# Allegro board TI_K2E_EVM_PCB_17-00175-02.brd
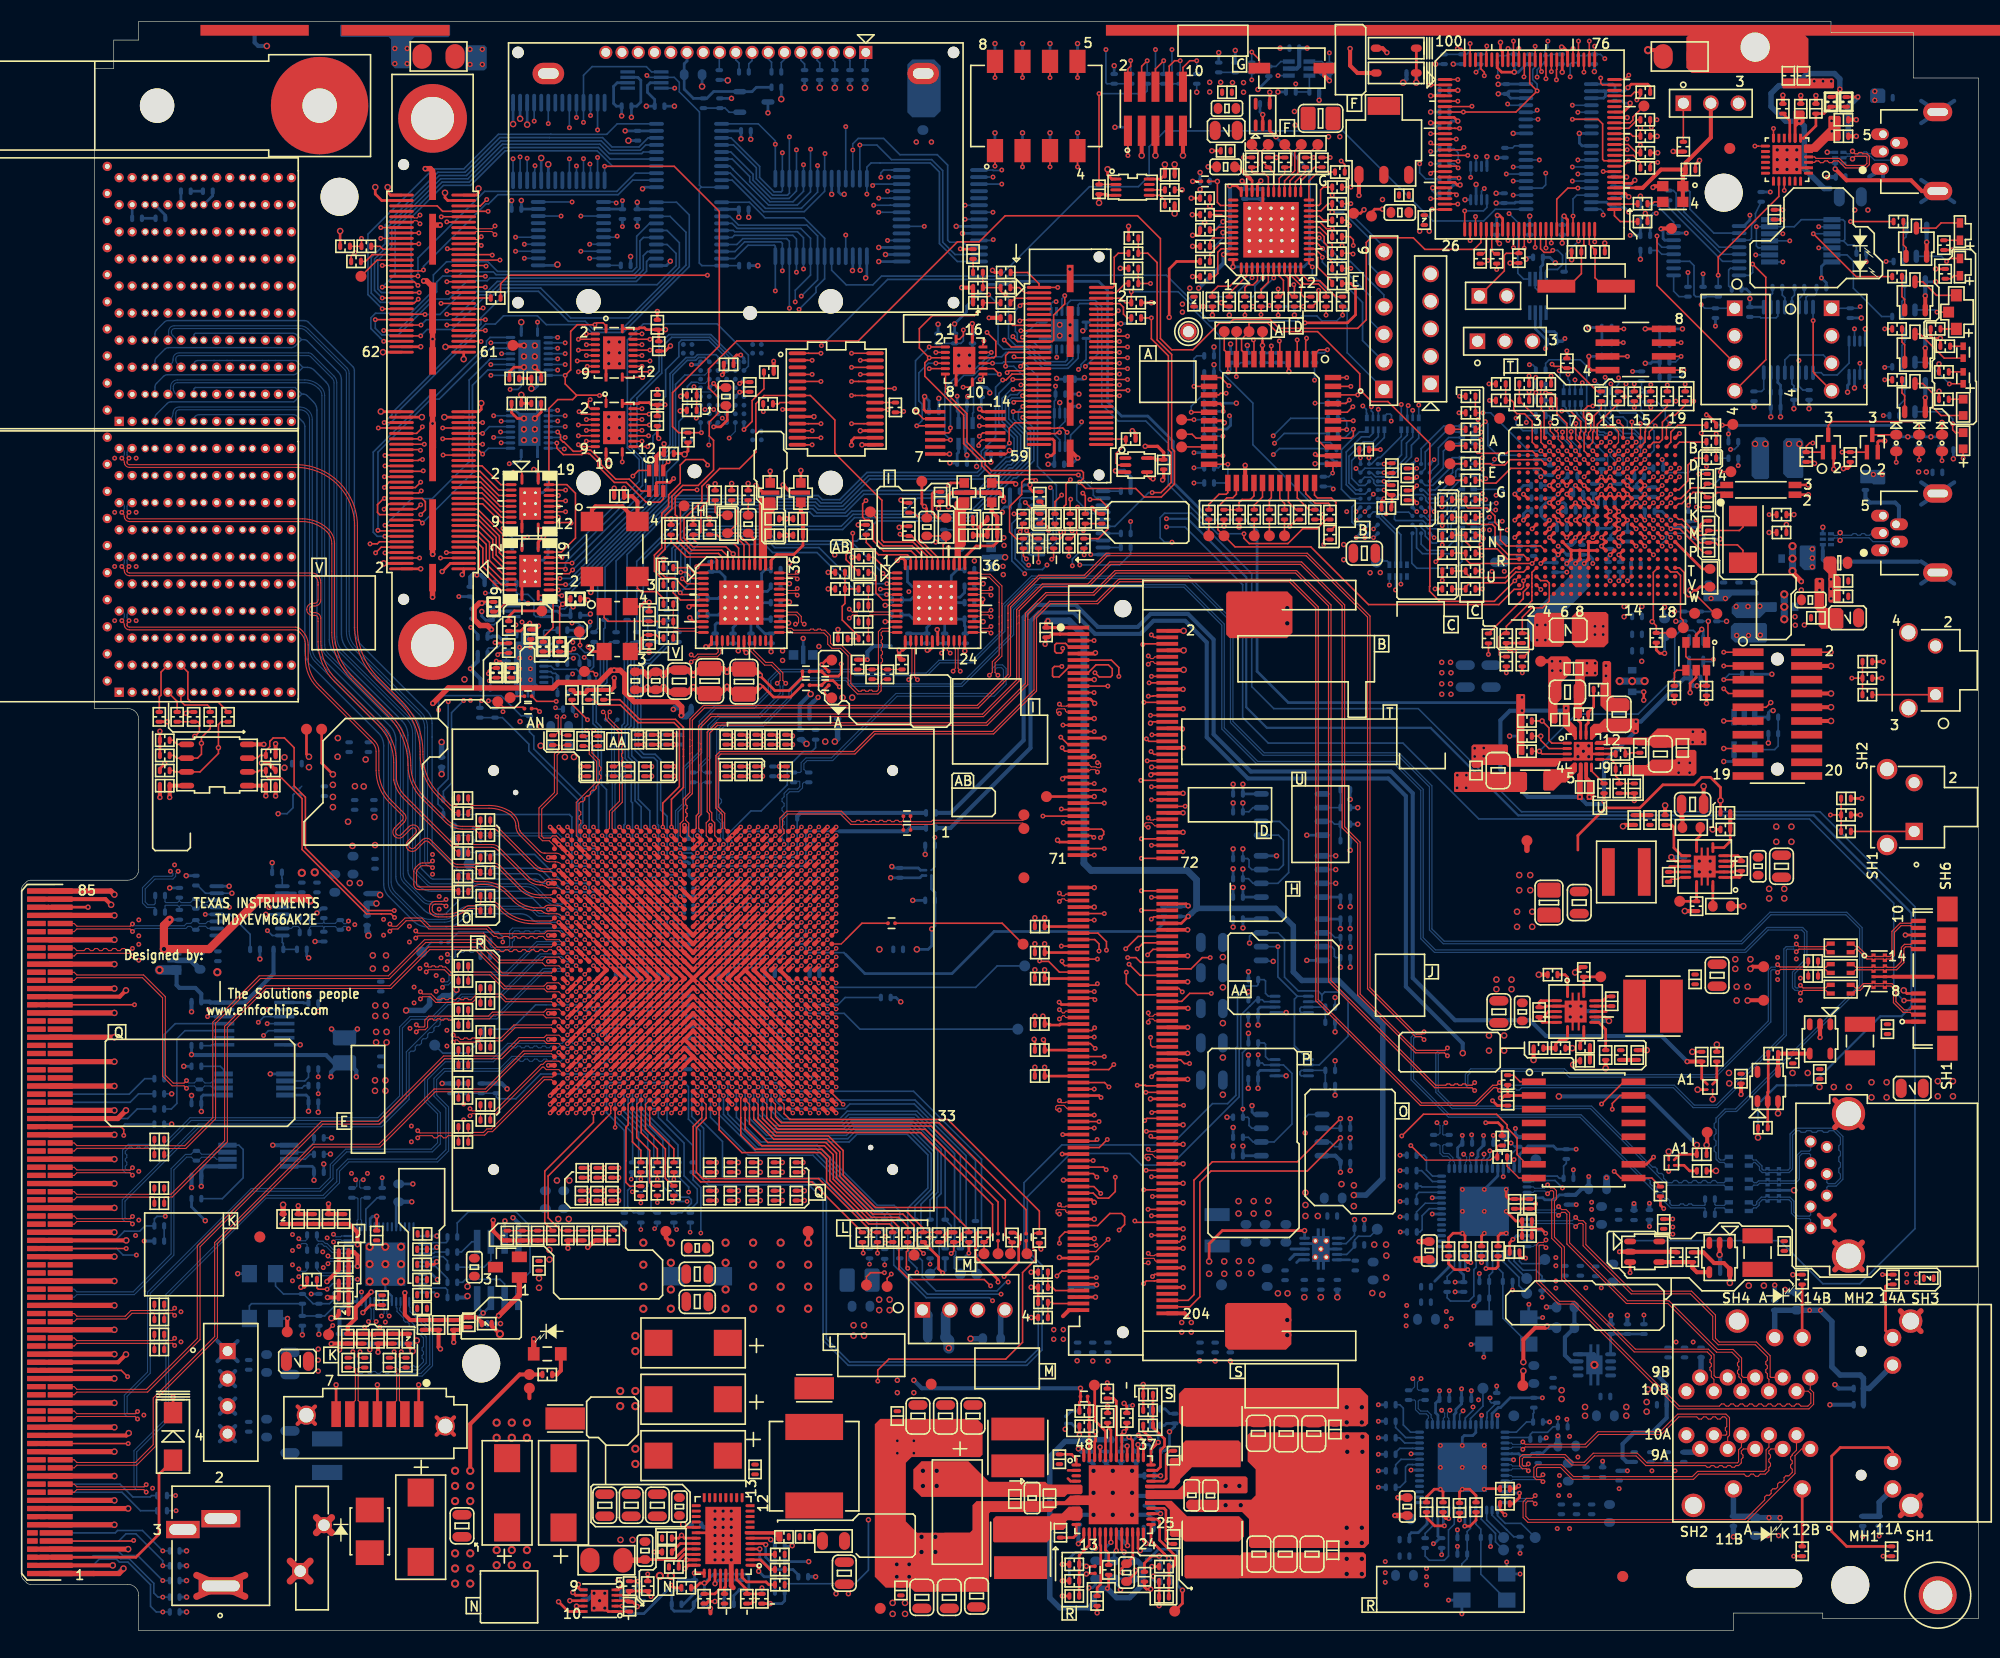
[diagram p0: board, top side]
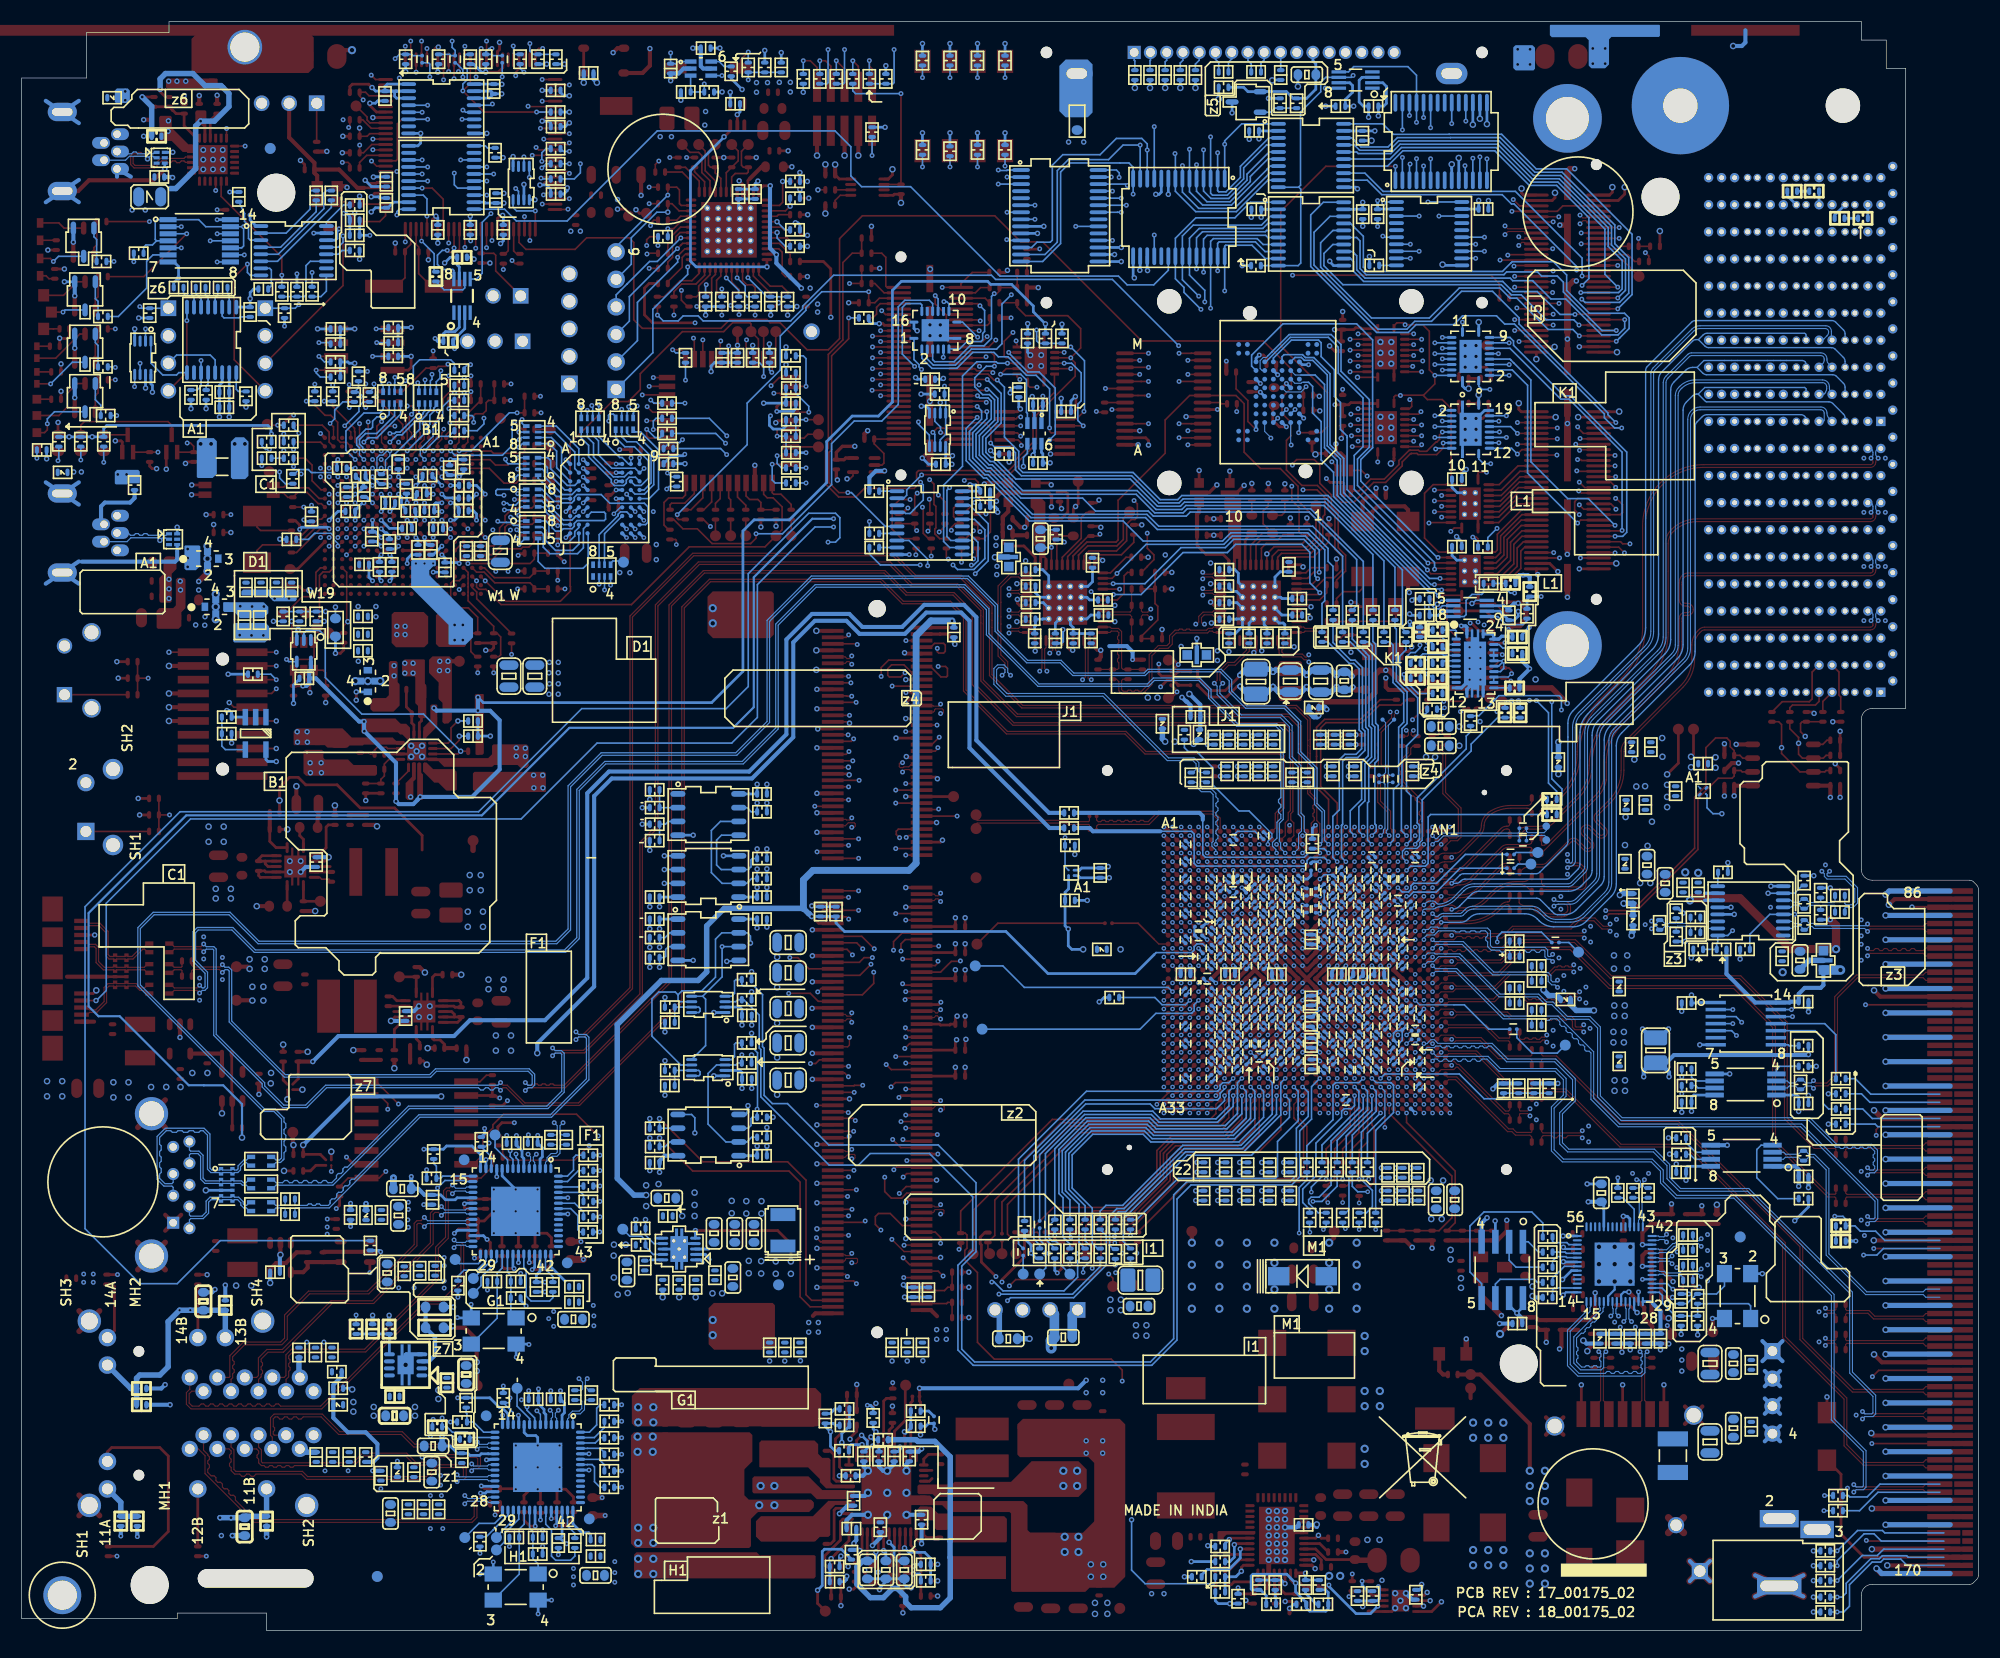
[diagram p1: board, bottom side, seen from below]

Outline 180.6 x 148.5 mm; copper layers: TOP, L2_GND1, L3_SIG1, L4_PWR1, L5_SIG2, L6_GND2, L7_GND3, L8_SIG3, L9_PWR2, L10_SIG4, L11_GND4, BOTTOM. Coordinates in mm from the lower left corner of the outline.
Outline path: 0,68.43 0,5.06 arc(0.04,4.87) 0.14,4.71 0.45,4.4 arc(0.62,4.29) 0.81,4.25 9.8,4.25 arc(10.51,3.96) 10.8,3.25 10.8,0 158,0 158,1.6 166.24,1.6 166.24,1.1 180.6,1.1 180.6,143.3 174.6,143.3 174.6,147.5 167,147.5 167,148.5 10.8,148.5 10.8,146.8 8.5,146.8 8.5,144.2 6.7,144.2 6.7,85.1 9.8,85.1 arc(10.51,84.81) 10.8,84.1 10.8,70.25 arc(10.51,69.54) 9.8,69.25 0.81,69.25 arc(0.62,69.21) 0.45,69.1 0.15,68.8 arc(0.04,68.63) 0,68.43

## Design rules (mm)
net group AMC4_PCIE0_RX0N: nets AMC4_PCIE0_RX0N N56425303
net group AMC4_PCIE0_RX0P: nets AMC4_PCIE0_RX0P N56425300
net group AMC4_PCIE0_TX0N: nets AMC4_PCIE0_TX0N AMC4_PCIE0_TX0N_R
net group AMC4_PCIE0_TX0P: nets AMC4_PCIE0_TX0P AMC4_PCIE0_TX0P_R
net group AMC5_PCIE0_RX1N: nets AMC5_PCIE0_RX1N N56425297
net group AMC5_PCIE0_RX1P: nets AMC5_PCIE0_RX1P N56425294
net group AMC5_PCIE0_TX1N: nets AMC5_PCIE0_TX1N AMC5_PCIE0_TX1N_R
net group AMC5_PCIE0_TX1P: nets AMC5_PCIE0_TX1P AMC5_PCIE0_TX1P_R
net group CPLD_D0: nets CPLD_D0 EMA_D0
net group CPLD_D1: nets CPLD_D1 EMA_D1
net group CPLD_WEN: nets CPLD_WEN N17968119
net group DIFF25M_CLK_REF: nets 25M_CLK_REFN 25M_CLK_REFP
net group DIFF25M_SEC_REF: nets 25M_SEC_REFN 25M_SEC_REFP
net group DIFFAMC0_SGMII2_RX_D: nets AMC0_SGMII2_RX_DN AMC0_SGMII2_RX_DP
net group DIFFAMC0_SGMII2_TX_D: nets AMC0_SGMII2_TX_DN AMC0_SGMII2_TX_DP
net group DIFFAMC1_SGMII3_RX_D: nets AMC1_SGMII3_RX_DN AMC1_SGMII3_RX_DP
net group DIFFAMC1_SGMII3_TX_D: nets AMC1_SGMII3_TX_DN AMC1_SGMII3_TX_DP
net group DIFFAMC2_SATA0_RX_D: nets AMC2_SATA0_RX_DN AMC2_SATA0_RX_DP
net group DIFFAMC2_SATA0_TX_D: nets AMC2_SATA0_TX_DN AMC2_SATA0_TX_DP
net group DIFFCORECLK: nets CORECLKN CORECLKP
net group DIFFCOREPLLOBSCLK: nets SOC_RSV002 SOC_RSV003
net group DIFFDDR3_CLK: nets DDR3_CLKN DDR3_CLKP
net group DIFFDDR3APLLOBSCLK: nets SOC_RSV004 SOC_RSV005
net group DIFFHYPER0_LINK_CLK: nets HYPER0_LINK_CLKN HYPER0_LINK_CLKP
net group DIFFNETCPCLK: nets NETCPCLKN NETCPCLKP
net group DIFFPAIR0: nets PHY1_MDI0_N PHY1_MDI0_P
net group DIFFPAIR1: nets PHY1_MDI1_N PHY1_MDI1_P
net group DIFFPAIR2: nets PHY1_MDI2_N PHY1_MDI2_P
net group DIFFPAIR3: nets PHY1_MDI3_N PHY1_MDI3_P
net group DIFFPAIR4: nets PHY2_MDI0_N PHY2_MDI0_P
net group DIFFPAIR5: nets PHY2_MDI1_N PHY2_MDI1_P
net group DIFFPAIR6: nets PHY2_MDI2_N PHY2_MDI2_P
net group DIFFPAIR7: nets PHY2_MDI3_N PHY2_MDI3_P
net group DIFFPAIR8: nets N18287363 N18287374
net group DIFFPAIR9: nets N17624377 N17624382
net group DIFFPAIR10: nets NETCPCLKN_R NETCPCLKP_R
net group DIFFPAIR21: nets UTCA_SGMII7_RX_DN_R UTCA_SGMII7_RX_DP_R
net group DIFFPAIR22: nets UTCA_SGMII6_RX_DN_R UTCA_SGMII6_RX_DP_R
net group DIFFPAIR23: nets UTCA_SGMII5_RX_DN_R UTCA_SGMII5_RX_DP_R
net group DIFFPAIR24: nets UTCA_SGMII4_RX_DN_R UTCA_SGMII4_RX_DP_R
net group DIFFPAIR25: nets AMC1_SGMII3_RX_DN_R AMC1_SGMII3_RX_DP_R
net group DIFFPAIR26: nets AMC0_SGMII2_RX_DN_R AMC0_SGMII2_RX_DP_R
net group DIFFPAIR27: nets SOC_SGMII1_RXN_R SOC_SGMII1_RXP_R
net group DIFFPAIR28: nets SOC_SGMII0_RXN_R SOC_SGMII0_RXP_R
net group DIFFPAIR33: nets N66223400 N66223405
net group DIFFPAIR34: nets USB_CLKN_R USB_CLKP_R
net group DIFFPAIR35: nets N17624472 N17624476
net group DIFFPAIR36: nets N18643297 N18643299
net group DIFFPAIR39: nets PCIE0CLKN_M PCIE0CLKP_M
net group DIFFPAIR40: nets TSREFCLKN_R TSREFCLKP_R
net group DIFFPAIR43: nets N18643296 N18643298
net group DIFFPAIR44: nets TXN_1 TXP_1
net group DIFFPAIR45: nets N19714197 N19714199
net group DIFFPAIR46: nets RXN_1 RXP_1
net group DIFFPAIR47: nets N19714193 N19714195
net group DIFFPAIR48: nets N19630686 N19630689
net group DIFFPAIR51: nets PCIECLKN_R PCIECLKP_R
net group DIFFPAIR52: nets PCIECLKN_MR PCIECLKP_MR
net group DIFFPAIR53: nets N17684391 N17684393
net group DIFFPAIR54: nets N17684395 N17684397
net group DIFFPAIR57: nets N18643300 N18643301
net group DIFFPAIR58: nets USB1_RXN_R USB1_RXP_R
net group DIFFPAIR59: nets USB1_TXN_R USB1_TXP_R
net group DIFFPAIR60: nets USB1DN_R USB1DP_R
net group DIFFPAIR61: nets N17665181 N20256822
net group DIFFPAIR65: nets N14877032 N17626857
net group DIFFPAIR66: nets USB_RXN_R USB_RXP_R
net group DIFFPAIR67: nets USBDN_R USBDP_R
net group DIFFPAIR68: nets N17664197 N17664207
net group DIFFPAIR69: nets N20256439 N20256446
net group DIFFPAIR70: nets XDS_USB_DM XDS_USB_DP
net group DIFFPAIR71: nets TCLKD_N_C TCLKD_P_C
net group DIFFPAIR72: nets N18358937 N18358939
net group DIFFPAIR73: nets N16997326 N16997342
net group DIFFPAPLLOBSCLK: nets SOC_RSV006 SOC_RSV007
net group DIFFPCIE0CLK: nets PCIE0CLKN PCIE0CLKP
net group DIFFPCIE1CLK: nets PCIE1CLKN PCIE1CLKP
net group DIFFPCIE_REF_CLK_: nets PCIE_REF_CLK_N PCIE_REF_CLK_P
net group DIFFRSV_CLK: nets RSV_CLKN RSV_CLKP
net group DIFFSATA_CLK: nets SATA_CLKN SATA_CLKP
net group DIFFSGMIICLK: nets SGMIICLKN SGMIICLKP
net group DIFFSOC_SGMII0_RX: nets SOC_SGMII0_RXN SOC_SGMII0_RXP
net group DIFFSOC_SGMII0_TX: nets SOC_SGMII0_TXN SOC_SGMII0_TXP
net group DIFFSOC_SGMII1_RX: nets SOC_SGMII1_RXN SOC_SGMII1_RXP
net group DIFFSOC_SGMII1_TX: nets SOC_SGMII1_TXN SOC_SGMII1_TXP
net group DIFFTCLKA_TSIP0CLKA_: nets TCLKA_TSIP0CLKA_N TCLKA_TSIP0CLKA_P
net group DIFFTCLKB_25MHZ_: nets TCLKB_25MHZ_N TCLKB_25MHZ_P
net group DIFFTCLKC_FS_: nets TCLKC_FS_N TCLKC_FS_P
net group DIFFTSREFCLK: nets TSREFCLKN TSREFCLKP
net group DIFFTSRX_CLK0: nets TSRX_CLK0N TSRX_CLK0P
net group DIFFTSRX_CLK1: nets TSRX_CLK1N TSRX_CLK1P
net group DIFFUSB0_RX: nets USB0_RXN USB0_RXP
net group DIFFUSB0_TX: nets USB0_TXN USB0_TXP
net group DIFFUSB0D: nets USB0DN USB0DP
net group DIFFUSB1_RX: nets USB1_RXN USB1_RXP
net group DIFFUSB1_TX: nets USB1_TXN USB1_TXP
net group DIFFUSB1D: nets USB1DN USB1DP
net group DIFFUSB_CLK: nets USB_CLKN USB_CLKP
net group DIFFXFICLK: nets XFICLKN XFICLKP
net group EMA_A4: nets EMA_A4 MEM_A4
net group EMA_A5: nets EMA_A5 MEM_A5
net group EMA_A6: nets EMA_A6 MEM_A6
net group EMA_A7: nets EMA_A7 MEM_A7
net group EMA_A8: nets EMA_A8 MEM_A8
net group EMA_A9: nets EMA_A9 MEM_A9
net group EMA_A10: nets EMA_A10 MEM_A10
net group EMA_A11: nets EMA_A11 MEM_A11
net group EMA_A12: nets EMA_A12 MEM_A12
net group EMA_BA0: nets EMA_BA0 MEM_BA0
net group EMA_BA1: nets EMA_BA1 MEM_BA1
net group EMA_D2: nets EMA_D2 MEM_D2
net group EMA_D3: nets EMA_D3 MEM_D3
net group EMA_D4: nets EMA_D4 MEM_D4
net group EMA_D5: nets EMA_D5 MEM_D5
net group EMA_D6: nets EMA_D6 MEM_D6
net group EMA_D7: nets EMA_D7 MEM_D7
net group EMA_D8: nets EMA_D8 MEM_D8
net group EMA_D9: nets EMA_D9 MEM_D9
net group EMA_D10: nets EMA_D10 MEM_D10
net group EMA_D11: nets EMA_D11 MEM_D11
net group EMA_D12: nets EMA_D12 MEM_D12
net group EMA_D13: nets EMA_D13 MEM_D13
net group EMA_D14: nets EMA_D14 MEM_D14
net group EMA_D15: nets EMA_D15 MEM_D15
net group HYPERLINK0_RXFLCLK: nets HYPERLINK0_RXFLCLK HYPERLINK0_RXFLCLK_R
net group HYPERLINK0_RXN0: nets HYPERLINK0_RXN0 HYPERLINK0_RXN0_C
net group HYPERLINK0_RXN1: nets HYPERLINK0_RXN1 HYPERLINK0_RXN1_C
net group HYPERLINK0_RXN2: nets HYPERLINK0_RXN2 HYPERLINK0_RXN2_C
net group HYPERLINK0_RXN3: nets HYPERLINK0_RXN3 HYPERLINK0_RXN3_C
net group HYPERLINK0_RXP0: nets HYPERLINK0_RXP0 HYPERLINK0_RXP0_C
net group HYPERLINK0_RXP1: nets HYPERLINK0_RXP1 HYPERLINK0_RXP1_C
net group HYPERLINK0_RXP2: nets HYPERLINK0_RXP2 HYPERLINK0_RXP2_C
net group HYPERLINK0_RXP3: nets HYPERLINK0_RXP3 HYPERLINK0_RXP3_C
net group HYPERLINK0_TXPMCLK: nets HYPERLINK0_TXPMCLK HYPERLINK0_TXPMCLK_R
net group MEM_CASN: nets MEM_CASN N25565163
net group MEM_CKE: nets MEM_CKE N25551369
net group MEM_CLK: nets MEM_CLK N25551345
net group MEM_CS0N: nets MEM_CS0N N25551640
net group MEM_RASN: nets MEM_RASN N25551410
net group MEM_WE_DQM0N: nets MEM_WE_DQM0N N25619366
net group MEM_WE_DQM1N: nets MEM_WE_DQM1N N25619369
net group PCIE1_RX1N: nets N16953910 PCIE1_RX1N
net group PCIE1_RX1P: nets N16953908 PCIE1_RX1P
net group PCIE1_RX2N: nets N16953906 PCIE1_RX2N
net group PCIE1_RX2P: nets N16953912 PCIE1_RX2P
net group PCIE1_TX1N: nets PCIE1_TX1N PCIE1_TX1N_R
net group PCIE1_TX1P: nets PCIE1_TX1P PCIE1_TX1P_R
net group PCIE1_TX2N: nets PCIE1_TX2N PCIE1_TX2N_R
net group PCIE1_TX2P: nets PCIE1_TX2P PCIE1_TX2P_R
net group SOC_XFI_RX_DN0: nets SOC_XFI_RX_DN0 SOC_XFI_RX_DN0_R
net group SOC_XFI_RX_DN1: nets SOC_XFI_RX_DN1 SOC_XFI_RX_DN1_R
net group SOC_XFI_RX_DP0: nets SOC_XFI_RX_DP0 SOC_XFI_RX_DP0_R
net group SOC_XFI_RX_DP1: nets SOC_XFI_RX_DP1 SOC_XFI_RX_DP1_R
net group U298: nets PHY2_LED_0 PHY_RSTZ
net group 456: nets AVDDA2 FAN_PWM GND_3 MMC_PS_N0 N17655103 N17941980 PLL0_VDDA12 SOC_TEMP1 USB0DRVVBUS VBUS0 VBUS1 VBUS1_R VCC0V75 VCC0V75REF VCC3V3_MP_AMC
net group CPLD_A0: nets CPLD_A0
net group CPLD_A1: nets CPLD_A1
net group CPLD_A2: nets CPLD_A2
net group CPLD_A3: nets CPLD_A3
net group EMU_SIGNALS: nets EMU_RTCK EMU_TCK EMU_TCK_R EMU_TDI EMU_TDI_R EMU_TDO EMU_TDO_R EMU_TMS EMU_TMS_R EMU_TRST# EMU_TRST#_R SOC_EMU_00 SOC_EMU_00_R SOC_EMU_01 SOC_EMU_01_R SOC_EMU_02 SOC_EMU_02_R SOC_EMU_03 SOC_EMU_03_R SOC_EMU_04 SOC_EMU_04_R SOC_EMU_05 SOC_EMU_05_R SOC_EMU_06 SOC_EMU_06_R SOC_EMU_07 SOC_EMU_07_R SOC_EMU_08 SOC_EMU_08_R SOC_EMU_09 SOC_EMU_09_R SOC_EMU_10 SOC_EMU_10_R SOC_EMU_11 SOC_EMU_11_R SOC_EMU_12 SOC_EMU_12_R SOC_EMU_13 SOC_EMU_13_R SOC_EMU_14 SOC_EMU_14_R SOC_EMU_15 SOC_EMU_15_R SOC_EMU_16 SOC_EMU_16_R SOC_EMU_17 SOC_EMU_17_R SOC_EMU_18 SOC_EMU_18_R SOC_EMU_19 SOC_EMU_19_R SOC_EMU_20 SOC_EMU_20_R SOC_EMU_21 SOC_EMU_21_R SOC_EMU_22 SOC_EMU_22_R SOC_EMU_23 SOC_EMU_23_R SOC_EMU_24 SOC_EMU_24_R SOC_EMU_25 SOC_EMU_25_R SOC_EMU_26 SOC_EMU_26_R SOC_EMU_27 SOC_EMU_27_R SOC_EMU_28 SOC_EMU_28_R SOC_EMU_29 SOC_EMU_29_R SOC_EMU_30 SOC_EMU_30_R SOC_EMU_31 SOC_EMU_31_R SOC_EMU_32 SOC_EMU_32_R SOC_EMU_33 SOC_EMU_33_R SOC_TCK SOC_TDI SOC_TDO SOC_TMS SOC_TRST# SOC_TVD TDIS TRGRSTZ
net group HYPERLINKS_TX: nets HYPERLINK0_TXN0 HYPERLINK0_TXN1 HYPERLINK0_TXN2 HYPERLINK0_TXN3 HYPERLINK0_TXP0 HYPERLINK0_TXP1 HYPERLINK0_TXP2 HYPERLINK0_TXP3
net group HYPERLINKS_TX_50E: nets HYPERLINK0_TXPMDAT
net group NAND: nets SOC_EMIFA11 SOC_EMIFA12 SOC_EMIFCE0Z SOC_EMIFD0 SOC_EMIFD1 SOC_EMIFD2 SOC_EMIFD3 SOC_EMIFD4 SOC_EMIFD5 SOC_EMIFD6 SOC_EMIFD7 SOC_EMIFOEZ SOC_EMIFWAIT0 SOC_EMIFWEZ
net group PVN: nets NAND_WPZ SOC_EMIFA00 SOC_EMIFA01 SOC_EMIFA02 SOC_EMIFA03 SOC_EMIFA04 SOC_EMIFA05 SOC_EMIFA06 SOC_EMIFA07 SOC_EMIFA08 SOC_EMIFA09 SOC_EMIFA10 SOC_EMIFA13 SOC_EMIFA14 SOC_EMIFA15 SOC_EMIFA16 SOC_EMIFA17 SOC_EMIFA19 SOC_EMIFA20 SOC_EMIFA21 SOC_EMIFA23 SOC_EMIFBE0Z SOC_EMIFCE1Z SOC_EMIFCE2Z SOC_EMIFCE3Z SOC_EMIFRNW SOC_EMIFWAIT1 SOC_PACLKSEL SOC_RSV011 SOC_RSV012 USB1_ID USB1DRVVBUS VBUS0_R
net group PWR: nets AVDD0 AVDD1 BPCAP DDR_DVDD18 IDAC_OUT N14466840 N19617114 N22090580 N22090583 N22090598 N22090602 N22090609 N22090615 N22090621 USB0_ID VAA1 VAA2_0 VAA2_1 VBAT VCC1V8_TCT VCC3_LCD VCC3_LCDBK VCCPLLA1A VCCPLLA1B VCCPLLA2A VCCPLLA2B
net group SDRAM_ADD: nets EMA_A0 EMA_A1 EMA_A2 EMA_A3
net group SGMII0_TX: nets UTCA_SGMII4_TX_DN UTCA_SGMII4_TX_DP UTCA_SGMII5_TX_DN UTCA_SGMII5_TX_DP UTCA_SGMII6_TX_DN UTCA_SGMII6_TX_DP UTCA_SGMII7_TX_DN UTCA_SGMII7_TX_DP
net group SOC_XFI: nets SOC_XFI_TX_DN0 SOC_XFI_TX_DN1 SOC_XFI_TX_DP0 SOC_XFI_TX_DP1
net group TRY: nets SOC_BOOTCOMPLETE SOC_HOUT SOC_LRESETNMIENZ SOC_LRESETZ SOC_NMIZ SOC_PORZ SOC_RESETFULLZ SOC_RESETZ
net group U297: nets PHY1_LED_1
net group UTCA_SGMII_RX: nets UTCA_SGMII4_RX_DN UTCA_SGMII4_RX_DP UTCA_SGMII5_RX_DN UTCA_SGMII5_RX_DP UTCA_SGMII6_RX_DN UTCA_SGMII6_RX_DP UTCA_SGMII7_RX_DN UTCA_SGMII7_RX_DP

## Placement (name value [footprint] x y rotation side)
AMC1  -  [GF-AMC-B]  2.05 36.75 90 top
B1  2200pF  [L_3P_70_63X35]  89.53 105.03 270 top
B2  2200pF  [L_3P_70_63X35]  87 105.03 270 top
B3  2200pF  [L_3P_70_63X35]  71.92 105.03 270 top
B4  2200pF  [L_3P_70_63X35]  69.09 105.03 270 top
B5  2200pF  [L_3P_70_63X35]  89.48 99.09 270 bottom
B6  2200pF  [L_3P_70_63X35]  72.14 90.04 180 bottom
B7  2200pF  [L_3P_70_63X35]  14.3 61.85 90 bottom
C1  100nF  [C0402]  111.25 141.99 90 top
C2  4.7uF  [C0603]  111.25 140.49 90 top
C3  1uF  [C0402]  165.61 140.46 180 top
C4  100nF  [C0402]  164.21 140.46 180 top
C5  100uF  [C1206-1]  119.89 139.57 180 top
C6  1uF  [C0402]  168.15 139.45 90 top
C7  100nF  [C0402]  168.15 137.92 90 top
C8  100nF  [C0402]  111.12 136.58 270 top
C9  4.7uF  [C0603]  111.12 135.1 270 top
C10  100nF  [C0402]  154.03 134.85 90 top
C11  100nF  [C0402]  105.97 134.37 90 top
C12  10pF  [C0402]  99.44 133.02 180 top
C13  100nF  [C0402]  127.58 132.49 270 top
C14  1uF  [C0603]  127.2 130.89 270 top
C15  100nF  [C0402]  161.77 130.68 180 top
C16  10pF  [C0402]  145.67 127.25 270 top
C17  10pF  [C0402]  143.51 127.25 270 top
C18  8.2pF  [C0402]  87.81 127.05 180 top
C19  1uF  [C0402]  58.67 120.52 180 top
C20  100nF  [C0402]  58.8 118.54 180 top
C21  100nF  [C0402]  65.25 116.87 270 top
C22  100nF  [C0402]  67.21 114.78 180 top
C23  100nF  [C0402]  47.5 115.57 270 top
C24  1uF  [C0402]  45.47 115.57 270 top
C25  100nF  [C0402]  58.67 113.59 0 top
C26  10uF  [C0603]  65 113.89 0 top
C27  1uF  [C0402]  47.5 113.26 90 top
C28  100nF  [C0402]  45.67 113.26 90 top
C29  1uF  [C0402]  58.67 111.63 0 top
C30  100nF  [C0402]  59.74 108.64 90 top
C31  100nF  [C0402]  105.41 107.62 0 top
C32  18pF  [C0402]  155.57 106.3 0 top
C33  100pF  [C0402]  65.53 104.78 180 top
C34  22nF  [C0402]  64.01 104.78 0 top
C35  100nF  [C0402]  55.14 104.7 270 top
C36  22nF  [C0402]  84.81 104.65 180 top
C37  18pF  [C0402]  155.57 104.14 180 top
C38  100nF  [C0402]  69.47 102.62 90 top
C39  100nF  [C0402]  89.59 102.62 270 top
C40  100nF  [C0402]  87.35 102.62 90 top
C41  100nF  [C0402]  71.66 102.62 270 top
C42  10uF  [C0603]  67.06 102.11 0 top
C43  33pF  [C0402]  155.7 101.98 0 top
C44  220pF  [C0603]  83.54 101.85 180 top
C45  10uF  [C0603]  86.56 100.77 180 bottom
C46  1uF  [C0402]  87.35 101.09 90 top
C47  1uF  [C0402]  69.47 101.09 90 top
C48  1uF  [C0402]  89.59 101.09 270 top
C49  1uF  [C0402]  71.66 101.09 270 top
C50  33pF  [C0402]  155.7 99.95 180 top
C51  10nF  [C0402]  168.15 96.88 270 top
C52  10uF  [C0603]  165.1 95.12 270 top
C53  100nF  [C0402]  77.7 94.61 90 top
C54  33pF  [C0402]  57.91 93.6 0 top
C55  10nF  [C0402]  165.61 93.47 270 top
C56  100nF  [C0402]  77.7 93.09 90 top
C57  100nF  [C0402]  94.56 92.12 180 top
C58  33pF  [C0402]  57.91 91.44 180 top
C59  1uF  [C0402]  75.79 91.54 270 top
C60  10nF  [C0402]  170.36 89.42 90 top
C61  100nF  [C0402]  143.24 88.77 270 top
C62  10uF  [C0603]  58.52 87.66 180 top
C63  10uF  [C0603]  56.64 87.66 180 top
C64  100uF  [C1206-1]  63.5 87.63 90 top
C65  47uF  [C0805]  60.71 87.63 0 top
C66  100uF  [C1206-1]  66.67 87.58 90 top
C67  100nF  [C0402]  155.51 86.74 0 top
C68  100nF  [C0402]  152.54 86.74 0 top
C69  22uF  [C0805]  142.68 86.61 90 top
C70  22uF  [C0805]  147.45 84.56 0 top
C71  1nF  [C0402]  141.99 84.07 90 top
C72  100nF  [C0402]  50.42 82.17 0 top
C73  100nF  [C0402]  49.02 82.17 0 top
C74  TBD  [C0402]  70.54 82.22 0 top
C75  TBD  [C0402]  69.16 82.22 180 top
C76  100nF  [C0402]  67.79 82.22 0 top
C77  2.2uF  [C0402]  66.4 82.22 0 top
C78  470nF  [C0402]  65.02 82.22 180 top
C79  470nF  [C0402]  59.56 82.22 0 top
C80  4.7uF  [C0402]  58.22 82.22 180 top
C81  220nF  [C0402]  56.85 82.22 180 top
C82  100nF  [C0402]  153.29 81.46 0 top
C83  100nF  [C0402]  53.21 82.09 0 top
C84  100nF  [C0402]  51.82 82.09 0 top
C85  22uF  [C0805]  151.26 80.9 180 top
C86  22uF  [C0805]  136.27 79.38 0 top
C87  100nF  [C0402]  134.24 79.38 180 top
C88  220nF  [C0402]  70.56 79.3 180 top
C89  1uF  [C0402]  67.77 79.3 180 top
C90  100nF  [C0402]  66.4 79.3 180 top
C91  100nF  [C0402]  65.02 79.3 0 top
C92  100nF  [C0402]  59.56 79.3 180 top
C93  100nF  [C0402]  57.53 79.3 0 top
C94  100nF  [C0402]  56.01 79.3 0 top
C95  100nF  [C0402]  54.61 79.3 0 top
C96  TBD  [C0402]  52.22 79.3 0 top
C97  100nF  [C0402]  22.99 77.98 90 top
C98  100nF  [C0402]  13.21 77.98 270 top
C99  100nF  [C0402]  144.27 77.85 90 top
C100  22pF  [C0402]  148.84 77.72 180 top
C101  100nF  [C0402]  40.77 76.83 270 top
C102  10nF  [C0402]  168.38 76.8 90 top
C103  27nF  [C0805]  154.23 76.25 270 top
C104  100nF  [C0402]  40.77 75.44 270 top
C105  10nF  [C0402]  151.69 74.8 180 top
C106  100nF  [C0402]  148.84 74.8 0 top
C107  100nF  [C0402]  42.8 74.8 270 top
C108  100nF  [C0402]  42.8 73.41 270 top
C109  100nF  [C0402]  40.77 73.15 270 top
C110  100nF  [C0402]  40.77 71.75 270 top
C111  100nF  [C0402]  42.8 71.37 270 top
C112  100nF  [C0402]  158.72 70.56 0 top
C113  22uF  [C0805]  162.43 70.54 180 top
C114  4.7uF  [C0603]  160.27 70.54 0 top
C115  100nF  [C0402]  42.8 69.98 270 top
C116  100nF  [C0402]  40.77 69.6 270 top
C117  100nF  [C0402]  152.02 69.56 180 top
C118  100nF  [C0402]  40.77 68.2 270 top
C119  100nF  [C0402]  42.8 67.82 270 top
C120  2.2uF  [C0402]  94.56 92.12 180 bottom
C121  22uF  [C0805]  143.76 67.18 180 top
C122  100uF  [C1206-1]  140.97 67.18 270 top
C123  100nF  [C0402]  42.8 66.42 270 top
C124  1uF  [C0402]  93.97 64.97 270 top
C125  1uF  [C0402]  93.97 62.57 270 top
C126  100nF  [C0402]  165.35 61.79 270 top
C127  100nF  [C0402]  40.77 61.34 270 top
C128  22uF  [C0805]  156.49 60.48 0 top
C129  100nF  [C0402]  165.35 60.4 270 top
C130  1uF  [C0402]  93.97 60.17 270 top
C131  100nF  [C0402]  154.46 60.1 180 top
C132  100nF  [C0402]  40.77 59.94 270 top
C133  100nF  [C0402]  42.8 59.31 270 top
C134  100nF  [C0402]  146.76 58.07 0 top
C135  100nF  [C0402]  42.8 57.91 270 top
C136  100nF  [C0402]  40.77 57.28 270 top
C137  4.7uF  [C0603]  138.51 57.1 180 top
C138  22uF  [C0805]  136.35 57.1 0 top
C139  100nF  [C0402]  140.06 57.07 180 top
C140  1uF  [C0402]  93.97 55.97 270 top
C141  100nF  [C0402]  40.77 55.88 270 top
C142  100nF  [C0402]  172.21 55.5 0 top
C143  100nF  [C0402]  42.8 55.24 270 top
C144  100uF  [CC1210]  169.67 54.4 270 top
C145  100nF  [C0402]  42.8 53.85 270 top
C146  100nF  [C0402]  40.77 53.59 270 top
C147  1uF  [C0402]  93.97 53.57 270 top
C148  100nF  [C0402]  149.12 53.11 180 top
C149  10nF  [C0402]  146.2 53.11 0 top
C150  1uF  [C0402]  156.46 52.96 180 top
C151  100nF  [C0402]  155.07 52.96 180 top
C152  10nF  [C0402]  144.3 52.58 270 top
C153  100nF  [C0402]  40.77 52.2 270 top
C154  1uF  [C0402]  165.96 51.36 0 top
C155  1uF  [C0402]  93.97 51.17 270 top
C156  100nF  [C0402]  158.7 50.93 0 top
C157  100nF  [C0402]  40.77 50.55 270 top
C158  100nF  [C0402]  40.77 49.15 270 top
C159  100nF  [C0402]  42.8 48.51 270 top
C160  100nF  [C0402]  42.8 47.12 270 top
C161  100nF  [C0402]  40.77 46.48 270 top
C162  100nF  [C0402]  12.7 45.32 90 top
C163  100nF  [C0402]  40.77 45.09 270 top
C164  100nF  [C0402]  155.07 43.94 90 top
C165  100nF  [C0402]  12.7 43.93 90 top
C166  220nF  [C0402]  71.5 42.75 180 top
C167  100nF  [C0402]  69.47 42.75 0 top
C168  2.2uF  [C0402]  67.44 42.75 0 top
C169  4.7uF  [C0402]  65.41 42.75 180 top
C170  100nF  [C0402]  63.5 42.75 180 top
C171  220nF  [C0402]  54.48 42.24 0 top
C172  100nF  [C0402]  53.11 42.24 180 top
C173  100nF  [C0402]  51.74 42.24 0 top
C174  1uF  [C0402]  155.07 42.42 90 top
C175  100nF  [C0402]  139.19 39.37 180 top
C176  100nF  [C0402]  12.7 40.82 90 top
C177  100nF  [C0402]  137.79 39.37 180 top
C178  220nF  [C0402]  71.5 40.13 180 top
C179  100nF  [C0402]  69.47 40.13 0 top
C180  220nF  [C0402]  67.44 40.13 180 top
C181  100nF  [C0402]  65.41 40.13 0 top
C182  220nF  [C0402]  63.5 40.13 180 top
C183  220nF  [C0402]  54.48 40.13 0 top
C184  TBD  [C0402]  53.09 40.13 180 top
C185  TBD  [C0402]  51.66 40.13 0 top
C186  100nF  [C0402]  155.83 39.81 90 bottom
C187  100nF  [C0402]  12.7 39.43 90 top
C188  100nF  [C0402]  138.94 37.8 270 top
C189  100nF  [C0402]  155.83 38.42 90 bottom
C190  1nF  [C0402]  29.72 37.97 0 top
C191  10nF  [C0402]  28.32 37.97 180 top
C192  100nF  [C0402]  26.92 37.97 180 top
C193  2.2uF  [C0402]  25.53 37.97 180 top
C194  100nF  [C0402]  151.56 37.52 180 top
C195  100nF  [C0402]  138.94 36.4 270 top
C196  100nF  [C0402]  37 36.6 270 top
C197  100nF  [C0402]  53.21 36.45 0 top
C198  10nF  [C0402]  51.82 36.45 0 top
C199  1nF  [C0402]  50.42 36.45 180 top
C200  100nF  [C0402]  49.02 36.45 0 top
C201  10nF  [C0402]  47.62 36.45 0 top
C202  1nF  [C0402]  46.23 36.45 180 top
C203  2.2uF  [C0402]  32.77 36.45 0 top
C204  100nF  [C0402]  137.79 34.92 90 top
C205  100nF  [C0402]  162.69 35.48 0 top
C206  10uF  [C0603]  62.36 35.31 270 top
C207  100nF  [C0402]  36.96 35.18 270 top
C208  10uF  [C0603]  129.92 35.06 180 top
C209  100nF  [C0402]  136.27 35 180 top
C210  100nF  [C0402]  134.75 35 180 top
C211  100nF  [C0402]  133.22 35 180 top
C212  100nF  [C0402]  131.7 35 180 top
C213  1nF  [C0402]  29.72 34.92 90 top
C214  100uF  [CC1210]  160.22 34.87 270 top
C215  100nF  [C0402]  36.96 33.78 270 top
C216  1uF  [C0402]  47.75 33.66 0 top
C217  10uF  [C0603]  41.78 33.53 0 top
C218  10nF  [C0402]  29.72 33.53 270 top
C219  22uF  [C0805]  62.36 32.89 90 top
C220  100nF  [C0402]  36.96 32.38 270 top
C221  100nF  [C0402]  29.72 32.13 270 top
C222  100nF  [C0402]  36.96 30.99 270 top
C223  2.2uF  [C0402]  29.72 30.73 270 top
C224  100nF  [C0402]  33.27 30.48 180 top
C225  47uF  [C0805]  62.36 30.35 90 top
C226  100nF  [C0402]  12.7 30.1 90 top
C227  100nF  [C0402]  36.96 29.72 270 top
C228  100nF  [C0402]  12.7 28.7 90 top
C229  2.2uF  [C0402]  41.27 28.45 0 top
C230  100nF  [C0402]  39.88 28.19 0 top
C231  10nF  [C0402]  38.48 28.19 0 top
C232  1nF  [C0402]  37.08 28.19 180 top
C233  100nF  [C0402]  12.7 27.32 90 top
C234  2.2uF  [C0402]  34.29 26.92 0 top
C235  100nF  [C0402]  32.89 26.92 0 top
C236  10nF  [C0402]  31.5 26.92 0 top
C237  1nF  [C0402]  30.1 26.92 180 top
C238  100nF  [C0402]  12.7 25.93 90 top
C239  100nF  [C0402]  35.47 24.71 180 top
C240  100nF  [C0402]  33.95 24.71 180 top
C241  100nF  [C0402]  31.66 24.71 180 top
C242  100nF  [C0402]  30.14 24.71 180 top
C243  100nF  [C0402]  80.82 19.79 0 top
C244  22uF  [C0805]  82.73 19.79 180 top
C245  430pF  [C0402]  103.97 21.77 270 top
C246  560pF  [CC0201_IPC7351_EINF]  98.06 21.59 180 top
C247  22uF  [C0805]  85.27 19.79 180 top
C248  100nF  [C0402]  121.21 18.54 0 top
C249  22uF  [C0805]  114.15 18.19 180 top
C250  22uF  [C0805]  119.25 18.16 180 top
C251  22uF  [C0805]  116.71 18.16 180 top
C252  22uF  [C0805]  87.81 19.79 180 top
C254  100nF  [C0402]  106.32 16.13 0 top
C256  100nF  [C0402]  95.78 15.8 0 top
C257  1uF  [C0402]  67.69 14.86 0 top
C259  100nF  [C0402]  136.91 13.08 270 top
C260  10uF  [C0603]  108 12.47 0 top
C261  1uF  [C0603]  109.73 12.45 0 top
C262  10uF  [C0603]  93.27 12.22 0 top
C263  100nF  [C0402]  94.87 12.19 0 top
C264  100nF  [C0402]  91.67 12.14 0 top
C265  100nF  [C0402]  136.91 11.68 270 top
C266  22uF  [C0805]  58.67 11.56 0 top
C267  22uF  [C0805]  56.26 11.56 0 top
C268  22uF  [C0805]  53.82 11.56 0 top
C269  10uF  [C0603]  127.89 11.43 180 top
C270  4.7uF  [C0603]  60.71 11.43 180 top
C271  100nF  [C0402]  134.24 11.37 180 top
C272  100nF  [C0402]  131.19 11.37 180 top
C273  100nF  [C0402]  129.67 11.37 180 top
C274  100nF  [C0402]  132.72 11.3 180 top
C275  22uF  [C0805]  40.64 9.65 180 top
C276  10pF  [C0805]  75.93 5.28 180 top
C277  100nF  [C0402]  72.26 8.64 90 top
C278  100nF  [C0402]  95.89 9.02 180 top
C279  2.2uF  [C0402]  59.56 8.51 270 top
C280  100nF  [C0402]  106.32 8.43 180 top
C281  4.7uF  [C0603]  57.53 7.37 180 top
C282  560pF  [CC0201_IPC7351_EINF]  99.06 5.59 270 top
C283  1uF  [C0603]  101.98 5.33 0 top
C284  1nF  [C0402]  103.63 4.95 180 top
C285  100nF  [C0402]  121.01 7.39 180 top
C286  22uF  [C0805]  119.1 7.04 0 top
C287  22uF  [C0805]  116.64 7.04 0 top
C288  22uF  [C0805]  114.2 7.04 0 top
C289  100nF  [C0402]  81.15 3.68 180 top
C290  100pF  [C0402]  97.16 3.17 270 top
C291  22uF  [C0805]  88.14 3.17 0 top
C292  82pF  [C0402]  105.44 3.1 270 top
C293  22uF  [C0805]  85.62 3.05 0 top
C294  22uF  [C0805]  83.08 3.05 0 top
C295  10nF  [C0402]  99.26 2.72 0 top
C296  100nF  [C0402]  56.11 2.19 0 top
C297  100nF  [C0402]  117.47 146.06 90 bottom
C298  2.2uF  [C0402]  139.19 145.03 180 bottom
C299  10nF  [C0402]  110.49 144.27 0 bottom
C300  100nF  [C0402]  120.7 144.17 180 bottom
C301  1uF  [C0402]  69.66 143.87 270 bottom
C302  1uF  [C0402]  66.66 143.87 270 bottom
C303  100nF  [C0402]  128.27 143.76 90 bottom
C304  4.7uF  [C0603]  61.98 143.61 270 bottom
C305  470nF  [C0402]  77.85 143.57 180 bottom
C306  470nF  [C0402]  76.45 143.57 180 bottom
C307  470nF  [C0402]  75.06 143.57 180 bottom
C308  470nF  [C0402]  73.66 143.57 180 bottom
C309  470nF  [C0402]  72.26 143.57 180 bottom
C310  1uF  [C0402]  64.39 143.57 180 bottom
C311  100nF  [C0402]  137.03 142.29 180 bottom
C312  100nF  [C0402]  131.32 142.16 90 bottom
C313  2.2uF  [C0402]  119.31 142.01 90 bottom
C314  100nF  [C0402]  147.07 141.64 180 bottom
C315  100nF  [C0402]  114.75 140.92 90 bottom
C316  100nF  [C0402]  58.88 140.7 270 bottom
C317  100nF  [C0402]  55.83 140.7 90 bottom
C318  10nF  [C0402]  131.32 140.16 90 bottom
C319  10nF  [C0402]  131.32 138.81 90 bottom
C320  100nF  [C0402]  66.85 138.42 270 bottom
C321  100nF  [C0402]  56.85 137.97 180 bottom
C322  100nF  [C0402]  167.89 134.16 90 bottom
C323  2.2uF  [C0402]  146.94 133.73 0 bottom
C324  100nF  [C0402]  160.56 132.33 0 bottom
C325  10nF  [C0402]  131.32 132.59 90 bottom
C326  100nF  [C0402]  114.43 132.59 180 bottom
C327  10nF  [C0402]  112.9 132.59 0 bottom
C328  100nF  [C0402]  153.42 132.46 180 bottom
C329  100nF  [C0402]  152.02 132.46 0 bottom
C330  100nF  [C0402]  136.83 132.21 0 bottom
C331  100nF  [C0402]  146.94 131.78 0 bottom
C332  100nF  [C0402]  45.67 131.21 90 bottom
C333  100nF  [C0402]  66.64 131.18 270 bottom
C334  100nF  [C0402]  56.82 130.73 180 bottom
C335  100nF  [C0402]  55.45 130.73 180 bottom
C336  1uF  [C0402]  149.86 130.18 90 bottom
C337  100nF  [C0402]  142.19 129.29 0 bottom
C338  100nF  [C0402]  139.19 129.29 0 bottom
C339  100nF  [C0402]  136.14 129.29 0 bottom
C340  100nF  [C0402]  149.86 128.78 90 bottom
C341  100nF  [C0402]  166.12 123.95 90 bottom
C342  100nF  [C0402]  164.08 123.95 90 bottom
C343  100nF  [C0402]  162.05 123.95 270 bottom
C344  100nF  [C0402]  158.29 123.83 90 bottom
C345  10nF  [C0402]  111.46 122.66 180 bottom
C346  100nF  [C0402]  159.51 121.7 0 bottom
C347  100nF  [C0402]  151.64 120.14 270 bottom
C348  100nF  [C0402]  87.76 119.25 180 bottom
C349  100nF  [C0402]  115.95 117.47 180 bottom
C350  2.2uF  [C0402]  114.53 117.47 180 bottom
C351  100nF  [C0402]  96.75 115.49 270 bottom
C352  1uF  [C0402]  161.89 114.3 270 bottom
C353  100nF  [C0402]  88.57 114.3 0 bottom
C354  100nF  [C0402]  109.6 113.28 270 bottom
C355  100nF  [C0402]  86.8 113.16 270 bottom
C356  100nF  [C0402]  161.89 112.9 270 bottom
C357  100nF  [C0402]  84.2 112.52 270 bottom
C358  1nF  [C0402]  109.6 108.71 270 bottom
C359  100nF  [C0402]  149.31 106.53 270 bottom
C360  22pF  [C0402]  157.99 108.2 270 bottom
C361  100nF  [C0402]  86.8 107.75 270 bottom
C362  100nF  [C0402]  120.9 107.7 90 bottom
C363  100nF  [C0402]  145.85 107.65 0 bottom
C364  100nF  [C0402]  145.09 105.39 180 bottom
C365  100nF  [C0402]  143.14 106.6 90 bottom
C366  100nF  [C0402]  141.1 107.09 0 bottom
C367  100nF  [C0402]  139.8 107.62 0 bottom
C368  100nF  [C0402]  95.76 107.65 270 bottom
C369  100nF  [C0402]  151.05 107.29 270 bottom
C370  100nF  [C0402]  147.4 106.27 0 bottom
C371  100nF  [C0402]  48.13 106.26 90 bottom
C372  100nF  [C0402]  139.78 105.69 90 bottom
C373  100nF  [C0402]  150.62 105.08 180 bottom
C374  100nF  [C0402]  91.67 105.16 90 bottom
C375  22uF  [C0805]  133.24 88.09 180 bottom
C376  22uF  [C0805]  135.63 88.09 180 bottom
C377  100nF  [C0402]  149.02 105.08 0 bottom
C378  100nF  [C0402]  143.66 104.93 270 bottom
C379  100nF  [C0402]  139.8 104.52 90 bottom
C380  100nF  [C0402]  146.58 104.09 90 bottom
C381  100nF  [C0402]  144.73 103.35 90 bottom
C382  100nF  [C0402]  142.98 103.35 270 bottom
C383  100nF  [C0402]  139.8 103.35 90 bottom
C384  100nF  [C0402]  150.27 103.3 270 bottom
C385  100nF  [C0402]  153.85 102.82 180 bottom
C386  100nF  [C0402]  145.03 101.73 90 bottom
C387  100nF  [C0402]  142.16 101.7 270 bottom
C388  100nF  [C0402]  148.29 100.97 180 bottom
C389  220nF  [C0402]  155.7 100.71 270 bottom
C390  100nF  [C0402]  146.66 100.28 180 bottom
C391  100nF  [C0402]  48.13 100.04 90 bottom
C392  100nF  [C0402]  144.02 99.75 180 bottom
C393  100nF  [C0402]  142.82 99.75 180 bottom
C394  100nF  [C0402]  138.24 99.63 0 bottom
C395  100nF  [C0402]  139.55 99.63 0 bottom
C396  22uF  [C0805]  136.42 99.61 180 bottom
C397  100nF  [C0402]  81.76 98.55 180 bottom
C398  1uF  [C0402]  149 98.4 90 bottom
C399  100nF  [C0402]  147.57 98.17 180 bottom
C400  100nF  [C0402]  146.43 98.17 180 bottom
C401  100nF  [C0402]  63.63 98.17 180 bottom
C402  100nF  [C0402]  141.53 98.12 180 bottom
C403  100nF  [C0402]  87.48 97.92 90 bottom
C404  100nF  [C0402]  69.6 97.92 90 bottom
C405  100nF  [C0402]  87.48 96.39 90 bottom
C406  100nF  [C0402]  69.6 96.39 90 bottom
C407  100nF  [C0402]  158.51 96.28 180 bottom
C408  10nF  [C0402]  157.08 96.28 180 bottom
C409  1uF  [C0402]  155.68 96.28 180 bottom
C410  1nF  [C0402]  159.89 96.27 0 bottom
C411  100nF  [C0402]  62.87 95.25 270 bottom
C412  100nF  [C0402]  80.8 95.12 270 bottom
C413  100nF  [C0402]  87.48 94.87 90 bottom
C414  100nF  [C0402]  69.6 94.87 90 bottom
C415  100nF  [C0402]  80.75 93.73 270 bottom
C416  100nF  [C0402]  62.87 93.73 270 bottom
C417  100nF  [C0402]  43.33 93.7 180 bottom
C418  10nF  [C0402]  149.1 93.6 270 bottom
C419  100nF  [C0402]  87.48 93.34 90 bottom
C420  100nF  [C0402]  69.6 93.34 90 bottom
C421  10nF  [C0402]  160.04 93.26 180 bottom
C422  100nF  [C0402]  158.64 93.26 180 bottom
C423  100nF  [C0402]  51.1 93.7 270 bottom
C424  100nF  [C0402]  149.1 91.95 270 bottom
C425  100nF  [C0402]  87.1 91.57 0 bottom
C426  100nF  [C0402]  85.19 91.57 0 bottom
C427  100nF  [C0402]  83.54 91.57 0 bottom
C428  100nF  [C0402]  81.89 91.57 0 bottom
C429  100nF  [C0402]  69.17 91.57 0 bottom
C430  100nF  [C0402]  67.31 91.57 0 bottom
C431  100nF  [C0402]  65.66 91.57 0 bottom
C432  100nF  [C0402]  64.01 91.57 0 bottom
C433  1nF  [C0402]  149.1 90.42 90 bottom
C435  100nF  [C0402]  154.51 87.88 270 bottom
C436  10uF  [C0603]  58.52 87.66 0 bottom
C437  47uF  [C0805]  63.5 87.63 180 bottom
C438  47uF  [C0805]  60.71 87.63 180 bottom
C439  100uF  [C1206-1]  66.67 87.58 90 bottom
C441  4.7uF  [C0402]  72.26 84.33 270 bottom
C442  100nF  [C0402]  138.94 83.95 270 bottom
C443  10uF  [C0603]  49.66 83.44 270 bottom
C444  100nF  [C0402]  138.94 82.55 270 bottom
C445  220nF  [C0402]  70.54 82.22 180 bottom
C446  220nF  [C0402]  69.16 82.22 0 bottom
C447  100nF  [C0402]  67.79 82.22 180 bottom
C448  2.2uF  [C0402]  66.4 82.22 180 bottom
C449  100nF  [C0402]  65.02 82.22 180 bottom
C450  220nF  [C0402]  60.78 82.22 0 bottom
C451  100nF  [C0402]  59.44 82.22 180 bottom
C452  220nF  [C0402]  58.06 82.22 0 bottom
C453  10uF  [C0603]  49.66 81.66 270 bottom
C454  4.7uF  [C0402]  30.23 81.53 180 bottom
C455  1uF  [C0402]  25.4 80.01 270 bottom
C456  100nF  [C0402]  72.64 78.74 180 bottom
C457  100nF  [C0402]  71.25 78.74 180 bottom
C458  220nF  [C0402]  69.34 79.3 0 bottom
C459  1uF  [C0402]  67.77 79.3 0 bottom
C460  100nF  [C0402]  66.4 79.3 0 bottom
C461  100nF  [C0402]  65.02 79.3 180 bottom
C462  100nF  [C0402]  63.35 78.74 180 bottom
C463  100nF  [C0402]  61.95 78.74 180 bottom
C464  100nF  [C0402]  59.56 79.3 0 bottom
C465  100nF  [C0402]  57.53 79.3 180 bottom
C466  220nF  [C0402]  52.22 79.3 180 bottom
C467  100nF  [C0402]  27.94 77.47 180 bottom
C468  100nF  [C0402]  112.27 77.22 90 bottom
C469  4.7uF  [C0402]  30.73 76.2 180 bottom
C470  10nF  [CC0201_IPC7351_EINF]  65.98 73.36 90 bottom
C471  560pF  [CC0201_IPC7351_EINF]  68.78 72.96 0 bottom
C472  560pF  [CC0201_IPC7351_EINF]  73.18 72.56 90 bottom
C473  560pF  [CC0201_IPC7351_EINF]  55.98 71.36 0 bottom
C474  100nF  [C0402]  137.16 48.9 0 top
C475  100nF  [CC0201_IPC7351_EINF]  73.18 70.96 270 bottom
C476  10uF  [C0603]  30.58 70.64 0 bottom
C477  100nF  [CC0201_IPC7351_EINF]  55.58 70.16 90 bottom
C478  100nF  [C0402]  81.05 69.93 0 bottom
C479  560pF  [CC0201_IPC7351_EINF]  65.98 69.36 270 bottom
C480  10nF  [CC0201_IPC7351_EINF]  73.18 69.36 270 bottom
C481  100nF  [CC0201_IPC7351_EINF]  68.38 69.36 90 bottom
C482  10nF  [CC0201_IPC7351_EINF]  67.58 69.36 90 bottom
C483  560pF  [CC0201_IPC7351_EINF]  62.78 69.36 90 bottom
C484  10nF  [CC0201_IPC7351_EINF]  59.58 69.36 270 bottom
C485  10nF  [CC0201_IPC7351_EINF]  57.98 69.36 90 bottom
C486  10nF  [CC0201_IPC7351_EINF]  56.38 69.36 90 bottom
C487  560pF  [CC0201_IPC7351_EINF]  70.78 69.36 90 bottom
C488  10nF  [CC0201_IPC7351_EINF]  69.18 69.36 90 bottom
C489  10nF  [CC0201_IPC7351_EINF]  64.38 69.36 90 bottom
C490  10nF  [CC0201_IPC7351_EINF]  54.78 69.36 270 bottom
C491  100nF  [CC0201_IPC7351_EINF]  53.98 69.36 270 bottom
C492  10uF  [C0603]  28.91 68.96 0 bottom
C493  10nF  [C0402]  27.25 68.58 0 bottom
C494  10nF  [C0402]  25.86 68.58 0 bottom
C495  100nF  [CC0201_IPC7351_EINF]  69.98 68.56 270 bottom
C496  1000pF  [CC0201_IPC7351_EINF]  66.78 68.56 270 bottom
C497  100nF  [CC0201_IPC7351_EINF]  65.18 68.56 270 bottom
C498  10nF  [CC0201_IPC7351_EINF]  63.58 68.56 270 bottom
C499  10nF  [CC0201_IPC7351_EINF]  60.38 68.56 90 bottom
C500  100nF  [CC0201_IPC7351_EINF]  58.78 68.56 270 bottom
C501  100nF  [CC0201_IPC7351_EINF]  57.18 68.56 270 bottom
C502  560pF  [CC0201_IPC7351_EINF]  55.58 68.56 270 bottom
C503  100nF  [CC0201_IPC7351_EINF]  68.78 68.16 0 bottom
C504  10nF  [CC0201_IPC7351_EINF]  61.98 68.16 270 bottom
C505  100nF  [CC0201_IPC7351_EINF]  61.18 68.16 90 bottom
C506  100nF  [C0402]  12.78 67.83 270 bottom
C507  10nF  [CC0201_IPC7351_EINF]  73.18 67.76 270 bottom
C508  10nF  [CC0201_IPC7351_EINF]  59.58 67.76 90 bottom
C509  100nF  [CC0201_IPC7351_EINF]  57.98 67.76 90 bottom
C510  560pF  [CC0201_IPC7351_EINF]  70.78 67.76 90 bottom
C511  100nF  [CC0201_IPC7351_EINF]  65.98 67.76 90 bottom
C512  100nF  [CC0201_IPC7351_EINF]  64.38 67.76 90 bottom
C513  100nF  [CC0201_IPC7351_EINF]  62.78 67.76 90 bottom
C514  10nF  [CC0201_IPC7351_EINF]  54.78 67.76 90 bottom
C515  100nF  [C0402]  122.17 67.69 270 bottom
C516  100nF  [C0402]  112.27 67.69 90 bottom
C517  4.7uF  [C0402]  31.88 67.56 0 bottom
C518  1uF  [C0402]  83.85 67.39 90 bottom
C519  10nF  [CC0201_IPC7351_EINF]  69.98 66.96 270 bottom
C520  100nF  [CC0201_IPC7351_EINF]  68.38 66.96 270 bottom
C521  10nF  [CC0201_IPC7351_EINF]  66.78 66.96 270 bottom
C522  10nF  [CC0201_IPC7351_EINF]  65.18 66.96 270 bottom
C523  10nF  [CC0201_IPC7351_EINF]  63.58 66.96 270 bottom
C524  100nF  [CC0201_IPC7351_EINF]  60.38 66.96 270 bottom
C525  22nF  [CC0201_IPC7351_EINF]  58.78 66.96 270 bottom
C526  10nF  [CC0201_IPC7351_EINF]  57.18 66.96 270 bottom
C527  560pF  [CC0201_IPC7351_EINF]  55.58 66.96 270 bottom
C528  100nF  [CC0201_IPC7351_EINF]  61.98 66.6 270 bottom
C529  100nF  [CC0201_IPC7351_EINF]  61.16 66.57 90 bottom
C530  100nF  [C0402]  106.86 66.35 180 bottom
C531  2.2uF  [C0402]  105.44 66.35 0 bottom
C532  100nF  [C0402]  12.78 66.31 270 bottom
C533  10nF  [CC0201_IPC7351_EINF]  73.18 66.16 90 bottom
C534  560pF  [CC0201_IPC7351_EINF]  65.98 66.16 90 bottom
C535  100nF  [CC0201_IPC7351_EINF]  56.38 66.16 90 bottom
C536  560pF  [CC0201_IPC7351_EINF]  70.78 66.16 90 bottom
C537  100nF  [CC0201_IPC7351_EINF]  64.38 66.16 90 bottom
C538  100nF  [CC0201_IPC7351_EINF]  62.78 66.16 90 bottom
C539  100nF  [CC0201_IPC7351_EINF]  59.58 66.16 90 bottom
C540  100nF  [CC0201_IPC7351_EINF]  53.18 66.16 90 bottom
C541  100nF  [C0402]  122.17 65.66 270 bottom
C542  100nF  [C0402]  112.27 65.66 90 bottom
C543  10nF  [CC0201_IPC7351_EINF]  68.38 65.36 270 bottom
C544  10nF  [CC0201_IPC7351_EINF]  66.78 65.36 270 bottom
C545  100nF  [CC0201_IPC7351_EINF]  65.18 65.36 270 bottom
C546  100nF  [CC0201_IPC7351_EINF]  63.58 65.36 270 bottom
C547  100nF  [CC0201_IPC7351_EINF]  60.38 65.36 270 bottom
C548  560pF  [CC0201_IPC7351_EINF]  58.78 65.36 270 bottom
C549  10nF  [CC0201_IPC7351_EINF]  57.18 65.36 270 bottom
C550  560pF  [CC0201_IPC7351_EINF]  55.58 65.36 270 bottom
C551  100nF  [CC0201_IPC7351_EINF]  71.98 64.96 180 bottom
C552  10nF  [CC0201_IPC7351_EINF]  70.78 64.56 90 bottom
C553  10nF  [CC0201_IPC7351_EINF]  69.18 64.56 90 bottom
C554  10nF  [CC0201_IPC7351_EINF]  67.58 64.56 90 bottom
C555  10nF  [CC0201_IPC7351_EINF]  65.98 64.56 270 bottom
C556  TBD  [CC0201_IPC7351_EINF]  64.38 64.56 270 bottom
C557  100nF  [CC0201_IPC7351_EINF]  59.58 64.56 270 bottom
C558  22nF  [CC0201_IPC7351_EINF]  57.98 64.56 90 bottom
C559  100nF  [CC0201_IPC7351_EINF]  56.38 64.56 90 bottom
C560  100nF  [CC0201_IPC7351_EINF]  54.78 64.56 90 bottom
C561  100nF  [CC0201_IPC7351_EINF]  53.18 64.56 90 bottom
C562  10nF  [CC0201_IPC7351_EINF]  71.98 64.16 180 bottom
C563  TBD  [C0402]  61.58 63.78 180 bottom
C564  560pF  [CC0201_IPC7351_EINF]  73.18 63.76 270 bottom
C565  10nF  [CC0201_IPC7351_EINF]  69.98 63.76 270 bottom
C566  10nF  [CC0201_IPC7351_EINF]  68.38 63.76 270 bottom
C567  TBD  [CC0201_IPC7351_EINF]  66.78 63.76 270 bottom
C568  TBD  [CC0201_IPC7351_EINF]  65.18 63.76 270 bottom
C569  22nF  [CC0201_IPC7351_EINF]  60.38 63.76 270 bottom
C570  100nF  [CC0201_IPC7351_EINF]  58.78 63.76 270 bottom
C571  22nF  [CC0201_IPC7351_EINF]  57.18 63.76 270 bottom
C572  560pF  [CC0201_IPC7351_EINF]  55.58 63.76 270 bottom
C573  100nF  [C0402]  42.8 63.63 90 bottom
C574  22uF  [C0805]  109.86 63.5 90 bottom
C575  TBD  [CC0201_IPC7351_EINF]  65.98 62.96 270 bottom
C576  100nF  [CC0201_IPC7351_EINF]  70.78 62.96 90 bottom
C577  10nF  [CC0201_IPC7351_EINF]  69.18 62.96 90 bottom
C578  10nF  [CC0201_IPC7351_EINF]  67.58 62.96 90 bottom
C579  TBD  [CC0201_IPC7351_EINF]  64.38 62.96 270 bottom
C580  10nF  [CC0201_IPC7351_EINF]  59.58 62.96 90 bottom
C581  22nF  [CC0201_IPC7351_EINF]  57.98 62.96 90 bottom
C582  22nF  [CC0201_IPC7351_EINF]  56.38 62.96 90 bottom
C583  100nF  [CC0201_IPC7351_EINF]  53.18 62.96 90 bottom
C584  10nF  [C0402]  18.11 62.23 180 bottom
C585  100nF  [C0402]  42.8 62.23 90 bottom
C586  10nF  [CC0201_IPC7351_EINF]  69.98 62.16 270 bottom
C587  10nF  [CC0201_IPC7351_EINF]  68.38 62.16 270 bottom
C588  TBD  [CC0201_IPC7351_EINF]  66.78 62.16 270 bottom
C589  TBD  [CC0201_IPC7351_EINF]  65.18 62.16 270 bottom
C590  22nF  [CC0201_IPC7351_EINF]  58.78 62.16 270 bottom
C591  22nF  [CC0201_IPC7351_EINF]  57.18 62.16 270 bottom
C592  100nF  [CC0201_IPC7351_EINF]  55.58 62.16 270 bottom
C593  100nF  [CC0201_IPC7351_EINF]  53.98 62.16 270 bottom
C594  10uF  [C0603]  16.46 61.85 180 bottom
C595  10nF  [CC0201_IPC7351_EINF]  70.78 61.36 90 bottom
C596  TBD  [CC0201_IPC7351_EINF]  67.58 61.36 270 bottom
C597  TBD  [CC0201_IPC7351_EINF]  65.98 61.36 270 bottom
C598  100nF  [CC0201_IPC7351_EINF]  53.18 61.36 90 bottom
C599  100nF  [C0402]  40.77 61.34 90 bottom
C600  22uF  [C0805]  109.86 60.71 90 bottom
C601  4.7uF  [C0402]  73.18 60.56 90 bottom
C602  4.7uF  [C0402]  69.06 60.56 90 bottom
C603  TBD  [C0402]  64.74 60.56 90 bottom
C604  TBD  [C0402]  59.21 60.56 270 bottom
C605  TBD  [C0402]  57.25 60.56 270 bottom
C606  TBD  [C0402]  55.3 60.56 270 bottom
C607  100nF  [C0402]  40.77 59.94 90 bottom
C608  TBD  [CC0201_IPC7351_EINF]  66.78 59.76 270 bottom
C609  100nF  [CC0201_IPC7351_EINF]  53.98 59.76 270 bottom
C610  100nF  [C0402]  42.8 59.31 90 bottom
C611  100nF  [CC0201_IPC7351_EINF]  73.18 58.96 90 bottom
C612  560pF  [CC0201_IPC7351_EINF]  70.78 58.96 90 bottom
C613  560pF  [CC0201_IPC7351_EINF]  69.18 58.96 90 bottom
C614  TBD  [CC0201_IPC7351_EINF]  67.58 58.96 270 bottom
C615  TBD  [CC0201_IPC7351_EINF]  65.98 58.96 270 bottom
C616  100nF  [CC0201_IPC7351_EINF]  64.38 58.96 90 bottom
C617  22nF  [CC0201_IPC7351_EINF]  59.58 58.96 90 bottom
C618  22nF  [CC0201_IPC7351_EINF]  57.98 58.96 90 bottom
C619  22nF  [CC0201_IPC7351_EINF]  56.38 58.96 90 bottom
C620  560pF  [CC0201_IPC7351_EINF]  53.18 58.96 90 bottom
C621  560pF  [CC0201_IPC7351_EINF]  52.38 58.96 270 bottom
C622  560pF  [CC0201_IPC7351_EINF]  69.98 58.16 90 bottom
C623  TBD  [CC0201_IPC7351_EINF]  68.38 58.16 90 bottom
C624  TBD  [CC0201_IPC7351_EINF]  66.78 58.16 270 bottom
C625  TBD  [CC0201_IPC7351_EINF]  65.18 58.16 270 bottom
C626  47nF  [CC0201_IPC7351_EINF]  63.58 58.16 270 bottom
C627  10nF  [CC0201_IPC7351_EINF]  60.38 58.16 270 bottom
C628  22nF  [CC0201_IPC7351_EINF]  58.78 58.16 270 bottom
C629  22nF  [CC0201_IPC7351_EINF]  57.18 58.16 270 bottom
C630  100nF  [CC0201_IPC7351_EINF]  55.58 58.16 270 bottom
C631  100nF  [CC0201_IPC7351_EINF]  53.98 58.16 270 bottom
C632  TBD  [C0402]  61.58 58.14 0 bottom
C633  100nF  [C0402]  16.13 58.04 90 bottom
C634  100nF  [C0402]  42.8 57.91 90 bottom
C635  100nF  [C0402]  26.92 57.91 270 bottom
C636  22uF  [C0805]  109.86 57.4 90 bottom
C637  100nF  [CC0201_IPC7351_EINF]  70.78 57.36 90 bottom
C638  100nF  [CC0201_IPC7351_EINF]  69.18 57.36 90 bottom
C639  TBD  [CC0201_IPC7351_EINF]  67.58 57.36 270 bottom
C640  TBD  [CC0201_IPC7351_EINF]  65.98 57.36 270 bottom
C641  100nF  [CC0201_IPC7351_EINF]  64.38 57.36 90 bottom
C642  100nF  [CC0201_IPC7351_EINF]  62.78 57.36 90 bottom
C643  22nF  [CC0201_IPC7351_EINF]  59.58 57.36 90 bottom
C644  22nF  [CC0201_IPC7351_EINF]  57.98 57.36 90 bottom
C645  100nF  [CC0201_IPC7351_EINF]  56.38 57.36 90 bottom
C646  100nF  [CC0201_IPC7351_EINF]  54.78 57.36 90 bottom
C647  100nF  [CC0201_IPC7351_EINF]  53.18 57.36 90 bottom
C648  560pF  [CC0201_IPC7351_EINF]  52.38 57.36 270 bottom
C649  100nF  [C0402]  40.77 57.28 90 bottom
C650  100nF  [C0402]  113.67 56.77 90 bottom
C651  100nF  [CC0201_IPC7351_EINF]  69.98 56.56 90 bottom
C652  TBD  [CC0201_IPC7351_EINF]  68.38 56.56 90 bottom
C653  TBD  [CC0201_IPC7351_EINF]  66.78 56.56 270 bottom
C654  TBD  [CC0201_IPC7351_EINF]  65.18 56.56 270 bottom
C655  100nF  [CC0201_IPC7351_EINF]  63.58 56.56 270 bottom
C656  22nF  [CC0201_IPC7351_EINF]  60.38 56.56 270 bottom
C657  10nF  [CC0201_IPC7351_EINF]  58.78 56.56 270 bottom
C658  10nF  [CC0201_IPC7351_EINF]  57.18 56.56 270 bottom
C659  560pF  [CC0201_IPC7351_EINF]  53.98 56.56 90 bottom
C660  TBD  [C0402]  61.58 56.18 0 bottom
C661  100nF  [C0402]  120.78 56.14 270 bottom
C662  100nF  [C0402]  40.77 55.88 90 bottom
C663  10nF  [CC0201_IPC7351_EINF]  70.78 55.76 90 bottom
C664  100nF  [CC0201_IPC7351_EINF]  69.18 55.76 90 bottom
C665  47nF  [CC0201_IPC7351_EINF]  67.58 55.76 270 bottom
C666  10nF  [CC0201_IPC7351_EINF]  64.38 55.76 90 bottom
C667  10nF  [CC0201_IPC7351_EINF]  62.78 55.76 90 bottom
C668  10nF  [CC0201_IPC7351_EINF]  56.38 55.76 90 bottom
C669  100nF  [CC0201_IPC7351_EINF]  54.78 55.76 90 bottom
C670  560pF  [CC0201_IPC7351_EINF]  53.18 55.76 90 bottom
C671  10nF  [CC0201_IPC7351_EINF]  73.18 55.76 90 bottom
C672  100nF  [CC0201_IPC7351_EINF]  65.98 55.76 90 bottom
C673  100nF  [CC0201_IPC7351_EINF]  51.98 55.36 180 bottom
C674  10nF  [CC0201_IPC7351_EINF]  69.98 54.96 90 bottom
C675  560pF  [CC0201_IPC7351_EINF]  68.38 54.96 90 bottom
C676  100nF  [CC0201_IPC7351_EINF]  63.58 54.96 270 bottom
C677  100nF  [CC0201_IPC7351_EINF]  60.38 54.96 270 bottom
C678  560pF  [CC0201_IPC7351_EINF]  58.78 54.96 270 bottom
C679  TBD  [CC0201_IPC7351_EINF]  57.18 54.96 270 bottom
C680  100nF  [CC0201_IPC7351_EINF]  55.58 54.96 270 bottom
C681  100nF  [CC0201_IPC7351_EINF]  51.98 54.56 180 bottom
C682  22uF  [C0805]  109.86 54.23 90 bottom
C683  TBD  [C0402]  61.58 54.23 0 bottom
C684  10nF  [CC0201_IPC7351_EINF]  70.78 54.16 90 bottom
C685  100nF  [CC0201_IPC7351_EINF]  69.18 54.16 90 bottom
C686  47nF  [CC0201_IPC7351_EINF]  67.58 54.16 270 bottom
C687  47nF  [CC0201_IPC7351_EINF]  66.78 54.16 270 bottom
C688  10nF  [CC0201_IPC7351_EINF]  64.38 54.16 90 bottom
C689  10nF  [CC0201_IPC7351_EINF]  62.78 54.16 90 bottom
C690  22nF  [CC0201_IPC7351_EINF]  56.38 54.16 90 bottom
C691  10nF  [CC0201_IPC7351_EINF]  73.18 54.16 90 bottom
C692  TBD  [CC0201_IPC7351_EINF]  65.98 54.16 270 bottom
C693  TBD  [CC0201_IPC7351_EINF]  59.58 54.16 90 bottom
C694  22nF  [CC0201_IPC7351_EINF]  57.98 54.16 90 bottom
C695  100nF  [CC0201_IPC7351_EINF]  53.98 54.16 270 bottom
C696  100uF  [C1206-1]  29.79 53.54 90 bottom
C697  560pF  [CC0201_IPC7351_EINF]  69.98 53.36 90 bottom
C698  47nF  [CC0201_IPC7351_EINF]  68.38 53.36 270 bottom
C699  10nF  [CC0201_IPC7351_EINF]  65.18 53.36 270 bottom
C700  100nF  [CC0201_IPC7351_EINF]  63.58 53.36 270 bottom
C701  22nF  [CC0201_IPC7351_EINF]  58.78 53.36 270 bottom
C702  22nF  [CC0201_IPC7351_EINF]  57.18 53.36 270 bottom
C703  100nF  [CC0201_IPC7351_EINF]  55.58 53.36 270 bottom
C704  100nF  [CC0201_IPC7351_EINF]  53.18 53.36 270 bottom
C705  100nF  [CC0201_IPC7351_EINF]  70.78 52.56 90 bottom
C706  100nF  [CC0201_IPC7351_EINF]  69.18 52.56 90 bottom
C707  560pF  [CC0201_IPC7351_EINF]  64.38 52.56 270 bottom
C708  100nF  [CC0201_IPC7351_EINF]  62.78 52.56 270 bottom
C709  560pF  [CC0201_IPC7351_EINF]  59.58 52.56 90 bottom
C710  560pF  [CC0201_IPC7351_EINF]  56.38 52.56 270 bottom
C711  560pF  [CC0201_IPC7351_EINF]  53.98 52.56 270 bottom
C712  4.7uF  [C0402]  61.58 52.25 180 bottom
C713  100nF  [CC0201_IPC7351_EINF]  69.98 51.76 90 bottom
C714  560pF  [CC0201_IPC7351_EINF]  60.38 51.76 270 bottom
C715  1000pF  [CC0201_IPC7351_EINF]  57.98 51.76 90 bottom
C716  560pF  [CC0201_IPC7351_EINF]  55.58 51.76 270 bottom
C717  1000pF  [CC0201_IPC7351_EINF]  68.38 51.76 270 bottom
C718  560pF  [CC0201_IPC7351_EINF]  65.98 51.76 270 bottom
C719  10nF  [CC0201_IPC7351_EINF]  57.18 51.76 270 bottom
C720  100nF  [CC0201_IPC7351_EINF]  70.78 50.96 270 bottom
C721  560pF  [CC0201_IPC7351_EINF]  73.18 50.96 270 bottom
C722  100nF  [C0402]  113.67 50.93 90 bottom
C723  22uF  [C0805]  109.86 50.8 90 bottom
C724  100nF  [C0402]  120.78 50.3 270 bottom
C725  100nF  [CC0201_IPC7351_EINF]  51.58 50.16 270 bottom
C726  100nF  [C0402]  43.81 50.04 0 bottom
C727  10nF  [C0402]  42.42 50.04 0 bottom
C728  1nF  [C0402]  41.02 50.04 180 bottom
C729  10nF  [CC0201_IPC7351_EINF]  58.38 48.96 180 bottom
C730  100nF  [C0402]  26.92 48.77 270 bottom
C731  100nF  [C0402]  16.13 48.64 90 bottom
C732  100nF  [C0402]  131.75 45.29 180 bottom
C733  100nF  [C0402]  130.33 45.29 180 bottom
C734  100nF  [C0402]  133.43 44.98 270 bottom
C735  100nF  [C0402]  135.38 44.97 270 bottom
C736  100nF  [C0402]  112.27 43.81 90 bottom
C737  100nF  [C0402]  122.17 43.18 270 bottom
C738  220nF  [C0402]  71.5 42.75 0 bottom
C739  2.2uF  [C0402]  69.47 42.75 0 bottom
C740  470nF  [C0402]  67.44 42.75 180 bottom
C741  470nF  [C0402]  65.41 42.75 0 bottom
C742  1uF  [C0402]  63.5 42.75 180 bottom
C743  220nF  [C0402]  54.48 42.24 180 bottom
C744  100nF  [C0402]  53.11 42.24 0 bottom
C745  TBD  [C0402]  51.74 42.24 180 bottom
C746  100nF  [C0402]  27.43 42.29 270 bottom
C747  100nF  [C0402]  16.13 41.91 90 bottom
C748  10uF  [C0603]  145.47 40.77 270 bottom
C749  10uF  [C0603]  34.8 40.39 0 bottom
C750  100nF  [C0402]  71.5 40.13 0 bottom
C751  100nF  [C0402]  69.47 40.13 180 bottom
C752  100nF  [C0402]  67.44 40.13 0 bottom
C753  100nF  [C0402]  65.41 40.13 180 bottom
C754  100nF  [C0402]  63.5 40.13 0 bottom
C755  1uF  [C0402]  54.48 40.13 0 bottom
C756  TBD  [C0402]  53.09 40.13 0 bottom
C757  TBD  [C0402]  51.66 40.13 180 bottom
C758  10uF  [C0603]  121.06 39.9 90 bottom
C759  100nF  [C0402]  142.67 39.75 180 bottom
C760  10uF  [C0603]  50.04 39.75 180 bottom
C761  10uF  [C0603]  48.34 39.75 180 bottom
C762  100nF  [C0402]  150.24 38.35 180 bottom
C763  100nF  [C0402]  147.4 38.35 0 bottom
C764  10uF  [C0603]  145.82 38.3 0 bottom
C765  100nF  [C0402]  120.96 38.25 90 bottom
C766  10uF  [C0603]  116.69 36.65 0 bottom
C767  10uF  [C0603]  114.78 36.65 0 bottom
C768  10uF  [C0603]  113 36.65 0 bottom
C769  100nF  [C0402]  26.8 36.5 90 bottom
C770  100nF  [C0402]  26.8 35.1 90 bottom
C771  100nF  [C0402]  26.8 33.71 90 bottom
C772  100nF  [C0402]  123.09 33.68 180 bottom
C773  100nF  [C0402]  143.87 33.2 180 bottom
C774  100nF  [C0402]  142.44 33.2 180 bottom
C775  4.7uF  [C0603]  124.74 33.17 180 bottom
C776  1uF  [C0402]  145.29 33.15 180 bottom
C777  1uF  [C0402]  157.22 33.06 90 bottom
C778  4.7uF  [C0603]  146.86 32.99 180 bottom
C779  100nF  [C0402]  116.61 32.78 180 bottom
C780  10uF  [C0603]  114.96 32.58 180 bottom
C781  100uF  [C1206-1]  77.34 32.33 0 bottom
C782  100nF  [C0402]  26.8 32.31 90 bottom
C783  33pF  [C0402]  137.16 32.21 90 bottom
C784  33pF  [C0402]  135 32.21 270 bottom
C785  10nF  [C0402]  118.39 31.9 180 bottom
C786  100nF  [C0402]  129.62 31.72 90 bottom
C787  100nF  [C0402]  133.1 31.7 180 bottom
C788  220nF  [C0402]  131.57 31.7 180 bottom
C789  2.2uF  [C0402]  98.3 31.22 0 bottom
C790  100nF  [C0402]  96.9 31.22 180 bottom
C791  33pF  [C0402]  27.43 30.61 180 bottom
C792  1uF  [C0402]  129.62 30.3 90 bottom
C793  4.7uF  [C0603]  77.47 29.92 270 bottom
C794  10uF  [C0603]  129.67 28.71 90 bottom
C795  33pF  [C0402]  27.43 28.57 0 bottom
C796  100nF  [C0402]  42.55 28.32 270 bottom
C797  1uF  [C0603]  84.45 27.05 90 bottom
C798  1uF  [C0603]  89.53 26.92 90 bottom
C799  2.2uF  [C0402]  33.53 26.92 180 bottom
C800  100nF  [C0402]  32.13 26.92 180 bottom
C801  10nF  [C0402]  30.73 26.92 180 bottom
C802  1nF  [C0402]  29.34 26.92 0 bottom
C803  100nF  [C0402]  111.56 26.12 0 bottom
C804  100nF  [C0402]  110.16 26.12 0 bottom
C805  100nF  [C0402]  108.76 26.12 0 bottom
C806  1uF  [C0402]  100.25 26.12 180 bottom
C807  1uF  [C0402]  98.86 26.12 180 bottom
C808  1uF  [C0402]  97.46 26.12 180 bottom
C809  1nF  [C0402]  155.01 25.65 0 bottom
C810  10nF  [C0402]  153.48 25.65 0 bottom
C811  100nF  [C0402]  151.96 25.65 0 bottom
C812  22uF  [C0805]  24.77 24.64 0 bottom
C813  10uF  [C0603]  22.61 24.64 180 bottom
C814  100nF  [C0402]  20.95 24.51 180 bottom
C815  100nF  [C0402]  151.38 22.35 90 bottom
C816  100nF  [C0402]  129.54 21.72 180 bottom
C817  100nF  [C0402]  128.02 21.72 180 bottom
C818  100nF  [C0402]  133.35 21.34 270 bottom
